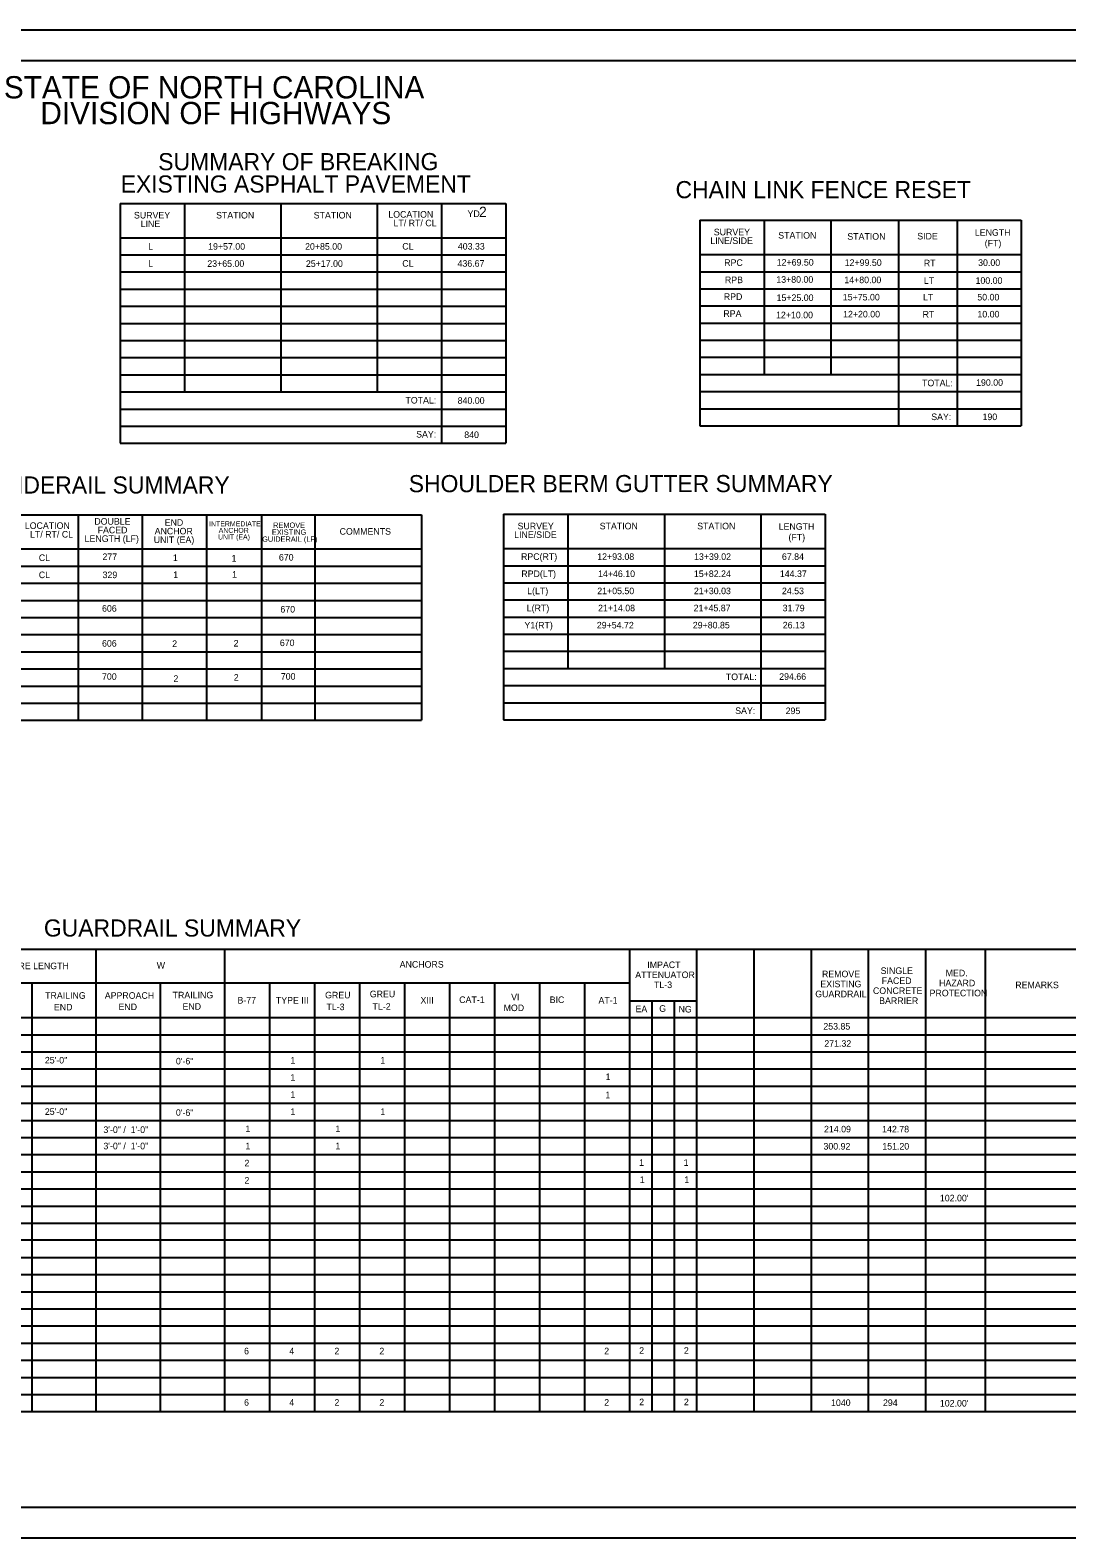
# Model space of a CAD drawing. Extents: x 2820318 to 2824860, y 680532 to 681838.
# Drawn here: x 2823312 to 2824069, y 680532 to 681632 of the extents above; entities that cross this region are included whole.
import ezdxf

# ---------------------------------------------------------------- set-up
doc = ezdxf.new("R2010")
doc.units = 0
for name, color, linetype in [('Default', 7, 'Continuous'), ('Sheet Cutting Line CELL', 7, 'Continuous'), ('Sheet Plot Border Inside CELL', 7, 'Continuous'), ('Sheet Plot Border Outside CELL', 7, 'Continuous'), ('Sheet Summary Combination CELL', 7, 'Continuous'), ('Sheet Summary Combination Grid CELL', 7, 'Continuous')]:
    doc.layers.add(name, color=color, linetype=linetype)

msp = doc.modelspace()

# ---------------------------------------------------------------- linework, layer by layer
at = {"layer": 'Default'}
msp.add_lwpolyline([(2822503.6, 681631.5), (2822503.6, 680531.5), (2824187.6, 680531.5), (2824187.6, 681631.5)], close=True, dxfattribs=at)
msp.add_lwpolyline([(2822503.6, 681631.5), (2822503.6, 680531.5), (2824187.6, 680531.5), (2824187.6, 681631.5)], close=True, dxfattribs=at)
at = {"layer": 'Sheet Cutting Line CELL'}
for p, q in [((2824187.6, 681631.5), (2822503.6, 681631.5)), ((2822503.6, 680531.5), (2824187.6, 680531.5))]:
    msp.add_line(p, q, dxfattribs=at)
at = {"layer": 'Sheet Plot Border Inside CELL'}
msp.add_lwpolyline([(2824183.1, 681609.1), (2822516.6, 681609.1), (2822516.6, 680554), (2824183.1, 680554)], close=True, dxfattribs=at)
at = {"layer": 'Sheet Plot Border Outside CELL'}
msp.add_lwpolyline([(2824187.6, 681631.5), (2822503.6, 681631.5), (2822503.6, 680531.5), (2824187.6, 680531.5)], close=True, dxfattribs=at)
at = {"layer": 'Sheet Summary Combination CELL'}
for p, q in [((2823519.3, 681505.1), (2823519.3, 681505.1)), ((2823534.6, 681505.2), (2823534.6, 681505.2)), ((2823540.2, 681505.1), (2823540.2, 681505.1)), ((2823525.6, 681505), (2823525.6, 681505)), ((2823942.2, 681492.7), (2823942.2, 681492.7)), ((2823948.4, 681492.6), (2823948.4, 681492.6)), ((2823957.5, 681492.8), (2823957.5, 681492.8)), ((2823963.1, 681492.7), (2823963.1, 681492.7)), ((2823799.1, 681278.3), (2823799.1, 681278.3)), ((2823805.3, 681278.2), (2823805.3, 681278.2)), ((2823814.4, 681278.4), (2823814.4, 681278.4)), ((2823820, 681278.3), (2823820, 681278.3))]:
    msp.add_line(p, q, dxfattribs=at)
at = {"layer": 'Sheet Summary Combination Grid CELL'}
for p, q in [((2823378.1, 681505.1), (2823659.4, 681505.1)), ((2823378.1, 681505.1), (2823378.1, 681330.1)), ((2823425, 681505.1), (2823425, 681367.6)), ((2823495.3, 681505.1), (2823495.3, 681367.6)), ((2823565.6, 681505.1), (2823565.6, 681367.6)), ((2823612.5, 681505.1), (2823612.5, 681330.1)), ((2823659.4, 681505.1), (2823659.4, 681330.1)), ((2823800.9, 681492.8), (2824035.4, 681492.8)), ((2823800.9, 681492.8), (2823800.9, 681342.8)), ((2823847.8, 681492.8), (2823847.8, 681380.3)), ((2823896.5, 681492.8), (2823896.5, 681380.3)), ((2823945.7, 681492.8), (2823945.7, 681342.8)), ((2823988.5, 681492.8), (2823988.5, 681342.8)), ((2824035.4, 681492.8), (2824035.4, 681342.8)), ((2823378.1, 681480.1), (2823659.4, 681480.1)), ((2823378.1, 681467.6), (2823659.4, 681467.6)), ((2823800.9, 681467.8), (2824035.4, 681467.8)), ((2823378.1, 681455.1), (2823659.4, 681455.1)), ((2823800.9, 681455.3), (2824035.4, 681455.3)), ((2823378.1, 681442.6), (2823659.4, 681442.6)), ((2823800.9, 681442.8), (2824035.4, 681442.8)), ((2823378.1, 681430.1), (2823659.4, 681430.1)), ((2823800.9, 681430.3), (2824035.4, 681430.3)), ((2823378.1, 681417.6), (2823659.4, 681417.6)), ((2823800.9, 681417.8), (2824035.4, 681417.8)), ((2823378.1, 681405.1), (2823659.4, 681405.1)), ((2823800.9, 681405.3), (2824035.4, 681405.3)), ((2823378.1, 681392.6), (2823659.4, 681392.6)), ((2823800.9, 681392.8), (2824035.4, 681392.8)), ((2823378.1, 681380.1), (2823659.4, 681380.1)), ((2823800.9, 681380.3), (2824035.4, 681380.3)), ((2823378.1, 681367.6), (2823659.4, 681367.6)), ((2823800.9, 681367.8), (2824035.4, 681367.8)), ((2823378.1, 681355.1), (2823659.4, 681355.1)), ((2823800.9, 681355.3), (2824035.4, 681355.3)), ((2823378.1, 681342.6), (2823659.4, 681342.6)), ((2823800.9, 681342.8), (2824035.4, 681342.8)), ((2823378.1, 681330.1), (2823659.4, 681330.1)), ((2823113, 681278), (2823598, 681278)), ((2823347.4, 681278), (2823347.4, 681128)), ((2823394.3, 681278), (2823394.3, 681128)), ((2823441.2, 681278), (2823441.2, 681128)), ((2823481.3, 681278), (2823481.3, 681128)), ((2823520.1, 681278), (2823520.1, 681128)), ((2823598, 681278), (2823598, 681128)), ((2823657.8, 681278.3), (2823892.3, 681278.3)), ((2823657.8, 681278.3), (2823657.8, 681128.3)), ((2823704.7, 681278.3), (2823704.7, 681165.8)), ((2823775.1, 681278.3), (2823775.1, 681165.8)), ((2823845.4, 681278.3), (2823845.4, 681128.3)), ((2823892.3, 681278.3), (2823892.3, 681128.3)), ((2823113, 681253), (2823598, 681253)), ((2823657.8, 681253.3), (2823892.3, 681253.3)), ((2823113, 681240.5), (2823598, 681240.5)), ((2823657.8, 681240.8), (2823892.3, 681240.8)), ((2823113, 681228), (2823551.1, 681228)), ((2823113, 681228), (2823598, 681228)), ((2823657.8, 681228.3), (2823892.3, 681228.3)), ((2823113, 681215.5), (2823598, 681215.5)), ((2823657.8, 681215.8), (2823892.3, 681215.8)), ((2823113, 681203), (2823598, 681203)), ((2823657.8, 681203.3), (2823892.3, 681203.3)), ((2823113, 681190.5), (2823598, 681190.5)), ((2823657.8, 681190.8), (2823892.3, 681190.8)), ((2823113, 681178), (2823598, 681178)), ((2823657.8, 681178.3), (2823892.3, 681178.3)), ((2823113, 681165.5), (2823598, 681165.5)), ((2823657.8, 681165.8), (2823892.3, 681165.8)), ((2823657.8, 681153.3), (2823892.3, 681153.3)), ((2823113, 681153), (2823598, 681153)), ((2823113, 681140.5), (2823551.1, 681140.5)), ((2823113, 681140.5), (2823598, 681140.5)), ((2823657.8, 681140.8), (2823892.3, 681140.8)), ((2823113, 681128), (2823598, 681128)), ((2823657.8, 681128.3), (2823892.3, 681128.3)), ((2822639.6, 680961.1), (2824083.4, 680961.1)), ((2823360.5, 680961.1), (2823360.5, 680711.1)), ((2823454.2, 680961.1), (2823454.2, 680711.1)), ((2823749.5, 680961.1), (2823749.5, 680711.1)), ((2823798.4, 680961.1), (2823798.4, 680711.1)), ((2823840.2, 680961.1), (2823840.2, 680711.1)), ((2823882, 680961.1), (2823882, 680711.1)), ((2823923.8, 680961.1), (2823923.8, 680711.1)), ((2823965.6, 680961.1), (2823965.6, 680623.6)), ((2824009, 680961.1), (2824009, 680623.6)), ((2823749.5, 680936.1), (2823272.4, 680936.1)), ((2823313.6, 680936.1), (2823313.6, 680711.1)), ((2823407.3, 680936.1), (2823407.3, 680711.1)), ((2823487, 680936.1), (2823487, 680711.1)), ((2823519.8, 680936.1), (2823519.8, 680711.1)), ((2823552.7, 680936.1), (2823552.7, 680711.1)), ((2823585.5, 680936.1), (2823585.5, 680711.1)), ((2823618.3, 680936.1), (2823618.3, 680711.1)), ((2823651.1, 680936.1), (2823651.1, 680711.1)), ((2823683.9, 680936.1), (2823683.9, 680711.1)), ((2823716.7, 680936.1), (2823716.7, 680711.1)), ((2823749.5, 680923.4), (2823798.1, 680923.4)), ((2823765.8, 680923.4), (2823765.9, 680711.1)), ((2823782.1, 680923.4), (2823782.2, 680711.1)), ((2822639.6, 680911.1), (2824083.4, 680911.1)), ((2822639.6, 680898.6), (2824083.4, 680898.6)), ((2822639.6, 680886.1), (2824083.4, 680886.1)), ((2822639.6, 680873.6), (2824083.4, 680873.6)), ((2822639.6, 680861.1), (2824083.4, 680861.1)), ((2822639.6, 680848.6), (2824083.4, 680848.6)), ((2822639.6, 680836.1), (2824083.4, 680836.1)), ((2822639.6, 680823.6), (2824083.4, 680823.6)), ((2822639.6, 680811.1), (2824083.4, 680811.1)), ((2822639.6, 680798.6), (2824083.4, 680798.6)), ((2822639.6, 680786.1), (2824083.4, 680786.1)), ((2822639.6, 680773.6), (2824083.4, 680773.6)), ((2822639.6, 680761.1), (2824083.4, 680761.1)), ((2822639.6, 680749), (2824083.4, 680749)), ((2822639.6, 680736.1), (2824083.4, 680736.1)), ((2822639.6, 680723.6), (2824083.4, 680723.6)), ((2822639.6, 680711.1), (2824083.4, 680711.1)), ((2823313.6, 680711.1), (2823313.6, 680623.6)), ((2823360.5, 680711.1), (2823360.5, 680623.6)), ((2823407.3, 680711.1), (2823407.3, 680623.6)), ((2823454.2, 680711.1), (2823454.2, 680623.6)), ((2823487, 680711.1), (2823487, 680623.6)), ((2823519.8, 680711.1), (2823519.8, 680623.6)), ((2823552.7, 680711.1), (2823552.7, 680623.6)), ((2823585.5, 680711.1), (2823585.5, 680623.6)), ((2823618.3, 680711.1), (2823618.3, 680623.6)), ((2823651.1, 680711.1), (2823651.1, 680623.6)), ((2823683.9, 680711.1), (2823683.9, 680623.6)), ((2823716.7, 680711.1), (2823716.7, 680623.6)), ((2823749.5, 680711.1), (2823749.5, 680623.6)), ((2823765.8, 680711.1), (2823765.8, 680623.6)), ((2823782.1, 680711.1), (2823782.2, 680623.6)), ((2823798.4, 680711.1), (2823798.4, 680623.6)), ((2823840.2, 680711.1), (2823840.2, 680623.6)), ((2823882, 680711.1), (2823882, 680623.6)), ((2823923.8, 680711.1), (2823923.8, 680623.6)), ((2822639.6, 680698.6), (2824083.4, 680698.6)), ((2822639.6, 680686.1), (2824083.4, 680686.1)), ((2822639.6, 680673.6), (2824083.4, 680673.6)), ((2822639.6, 680661.1), (2824083.4, 680661.1)), ((2822639.6, 680648.6), (2824083.4, 680648.6)), ((2822639.6, 680636.1), (2824083.4, 680636.1)), ((2822639.6, 680623.6), (2824083.4, 680623.6))]:
    msp.add_line(p, q, dxfattribs=at)

# ---------------------------------------------------------------- texts
at = {"layer": 'Sheet Summary Combination CELL'}
for s, height, p in [('STATE OF NORTH CAROLINA', 16.25, (2823293.3, 681581.7)), ('DIVISION OF HIGHWAYS', 16.25, (2823319.9, 681562.9)), ('SURVEY', 4.8, (2823388.2, 681494.1)), ('STATION', 4.8, (2823448.1, 681494.1)), ('STATION', 4.8, (2823519.3, 681494.1)), ('LOCATION', 4.8, (2823573.7, 681494.7)), ('LINE', 4.8, (2823393.1, 681487.8)), ('LT/ RT/ CL', 4.8, (2823577.5, 681488.4)), ('SURVEY', 4.8, (2823811.1, 681481.8)), ('STATION', 4.8, (2823858.1, 681479.4)), ('STATION', 4.8, (2823908.5, 681478.6)), ('SIDE', 4.8, (2823959.5, 681478.8)), ('LENGTH', 4.8, (2824001.5, 681481.5)), ('L', 4.8, (2823398.6, 681471.4)), ('19+57.00', 4.8, (2823442.3, 681471.3)), ('20+85.00', 4.8, (2823513, 681471.3)), ('CL', 4.8, (2823583.9, 681471.4)), ('403.33', 4.8, (2823624.4, 681471.4)), ('LINE/SIDE', 4.8, (2823808.6, 681475.5)), ('(FT)', 4.8, (2824008.7, 681473.7)), ('L', 4.8, (2823398.6, 681458.9)), ('23+65.00', 4.8, (2823441.7, 681458.8)), ('25+17.00', 4.8, (2823513.6, 681458.8)), ('CL', 4.8, (2823583.9, 681458.9)), ('436.67', 4.8, (2823624.2, 681458.9)), ('RPC', 4.8, (2823818.7, 681459.5)), ('12+69.50', 4.8, (2823857, 681459.7)), ('12+99.50', 4.8, (2823906.6, 681459.5)), ('RT', 4.8, (2823964.3, 681459.2)), ('30.00', 4.8, (2824003.9, 681459.5)), ('RPB', 4.8, (2823819.2, 681446.9)), ('13+80.00', 4.8, (2823856.7, 681447.2)), ('14+80.00', 4.8, (2823906.3, 681446.9)), ('LT', 4.8, (2823964.3, 681446.4)), ('100.00', 4.8, (2824002, 681446.4)), ('RPD', 4.8, (2823818.4, 681434.7)), ('15+75.00', 4.8, (2823905.2, 681434.3)), ('LT', 4.8, (2823963.7, 681434.3)), ('50.00', 4.8, (2824003.3, 681434.3)), ('15+25.00', 4.8, (2823856.9, 681433.9)), ('RPA', 4.8, (2823818.1, 681422.3)), ('12+10.00', 4.8, (2823856.5, 681421.3)), ('12+20.00', 4.8, (2823905.4, 681421.9)), ('RT', 4.8, (2823963.4, 681421.8)), ('10.00', 4.8, (2824003.4, 681421.9)), ('TOTAL:', 4.8, (2823963, 681371.7)), ('190.00', 4.8, (2824002.4, 681372)), ('TOTAL:', 4.8, (2823586.2, 681359.1)), ('840.00', 4.8, (2823624.3, 681358.9)), ('SAY:', 4.8, (2823969.7, 681347)), ('190', 4.8, (2824007.1, 681347)), ('SAY:', 4.8, (2823594, 681334.3)), ('840', 4.8, (2823629.1, 681333.9)), ('DOUBLE', 4.8, (2823359.3, 681270.7)), ('END', 4.8, (2823410.6, 681269.9)), ('LOCATION', 4.8, (2823308.6, 681267.6)), ('LT/ RT/ CL', 4.8, (2823312.4, 681261.3)), ('LENGTH (LF)', 4.8, (2823352.2, 681258.1)), ('FACED', 4.8, (2823361.7, 681264.4)), ('ANCHOR', 4.8, (2823403.3, 681263.6)), ('INTERMEDIATE ', 3.662, (2823443, 681269.5)), ('UNIT (EA)', 3.66, (2823449.5, 681259.9)), ('ANCHOR', 3.66, (2823450, 681264.7)), ('EXISTING', 3.89, (2823488.8, 681263.3)), ('REMOVE', 3.89, (2823489.7, 681268.4)), ('COMMENTS', 4.8, (2823538.2, 681263.4)), ('LINE/SIDE', 4.8, (2823665.5, 681261)), ('SURVEY', 4.8, (2823668, 681267.3)), ('STATION', 4.8, (2823727.9, 681267.3)), ('STATION', 4.8, (2823799, 681267.3)), ('LENGTH', 4.8, (2823858.4, 681267)), ('(FT)', 4.8, (2823865.6, 681259.2)), ('UNIT (EA)', 4.8, (2823402.6, 681257.3)), ('GUIDERAIL (LF)', 3.888, (2823481.7, 681258.2)), ('CL', 4.8, (2823318.8, 681244.2)), ('277', 4.8, (2823365.2, 681244.9)), ('1', 4.8, (2823416.6, 681244.2)), ('1', 4.8, (2823459.4, 681243.8)), ('670', 4.8, (2823493.9, 681244.5)), ('RPC(RT)', 4.8, (2823670.5, 681245)), ('12+93.08', 4.8, (2823726.1, 681245)), ('13+39.02', 4.8, (2823796.7, 681245)), ('67.84', 4.8, (2823860.8, 681245)), ('CL', 4.8, (2823318.8, 681231.7)), ('329', 4.8, (2823365.3, 681231.7)), ('1', 4.8, (2823416.8, 681231.8)), ('1', 4.8, (2823459.8, 681232)), ('RPD(LT)', 4.8, (2823670.7, 681232.5)), ('14+46.10', 4.8, (2823726.7, 681232.5)), ('15+82.24', 4.8, (2823796.6, 681232.5)), ('144.37', 4.8, (2823859.3, 681232.5)), ('L(LT)', 4.8, (2823675, 681220)), ('21+05.50', 4.8, (2823726.1, 681220)), ('21+30.03', 4.8, (2823796.6, 681220)), ('24.53', 4.8, (2823860.8, 681220)), ('606', 4.8, (2823364.9, 681207.2)), ('670', 4.8, (2823495, 681206.6)), ('L(RT)', 4.8, (2823674.7, 681207.5)), ('21+14.08', 4.8, (2823726.7, 681207.5)), ('21+45.87', 4.8, (2823796.4, 681207.5)), ('31.79', 4.8, (2823861.3, 681207.5)), ('Y1(RT)', 4.8, (2823673, 681195)), ('29+54.72', 4.8, (2823725.8, 681195)), ('29+80.85', 4.8, (2823795.8, 681195)), ('26.13', 4.8, (2823861.4, 681195)), ('606', 4.8, (2823364.9, 681181.7)), ('2', 4.8, (2823416.1, 681181.5)), ('2', 4.8, (2823460.9, 681181.8)), ('670', 4.8, (2823494.6, 681182.1)), ('700', 4.8, (2823364.9, 681157.5)), ('2', 4.8, (2823417, 681156)), ('2', 4.8, (2823461, 681156.9)), ('700', 4.8, (2823495.3, 681157.6)), ('TOTAL:', 4.8, (2823819.9, 681157.3)), ('294.66', 4.8, (2823858.8, 681157.5)), ('SAY:', 4.8, (2823826.7, 681132.6)), ('295', 4.8, (2823863.5, 681132.5)), ('GUARDRAIL SUMMARY', 12.5, (2823322.5, 680970.2)), ('FLARE LENGTH', 4.8, (2823292.2, 680946.4)), ('W', 4.8, (2823404.8, 680946.8)), ('ANCHORS', 4.8, (2823582, 680947.5)), ('ATTENUATOR', 4.8, (2823753.8, 680939.9)), ('IMPACT', 4.8, (2823762.6, 680947.2)), ('REMOVE', 4.8, (2823890, 680940.5)), ('SINGLE', 4.8, (2823932.8, 680942.9)), ('MED.', 4.8, (2823980.2, 680941.2)), ('TL-3', 4.8, (2823767.5, 680932.6)), ('EXISTING', 4.8, (2823888.8, 680933.2)), ('CONCRETE', 4.8, (2823927.2, 680928.3)), ('FACED', 4.8, (2823933.6, 680935.6)), ('HAZARD', 4.8, (2823975.4, 680933.9)), ('REMARKS', 4.8, (2824031, 680932.5)), ('TRAILING', 4.8, (2823323.4, 680924.8)), ('APPROACH', 4.8, (2823366.9, 680924.8)), ('TRAILING', 4.8, (2823416.4, 680925.1)), ('B-77', 4.8, (2823463.7, 680921.3)), ('TYPE III', 4.8, (2823491.7, 680921.3)), ('GREU', 4.8, (2823527.6, 680925.1)), ('GREU', 4.8, (2823560.2, 680925.9)), ('XIII', 4.8, (2823597.2, 680921.3)), ('CAT-1', 4.8, (2823625.4, 680921.7)), ('VI', 4.8, (2823663.3, 680923.7)), ('BIC', 4.8, (2823691.4, 680921.7)), ('AT-1', 4.8, (2823727, 680921.3)), ('GUARDRAIL', 4.8, (2823885.1, 680925.9)), ('BARRIER', 4.8, (2823931.7, 680921)), ('PROTECTION', 4.8, (2823968.5, 680926.6)), ('END', 4.8, (2823329.8, 680916.3)), ('END', 4.8, (2823376.9, 680916.5)), ('END', 4.8, (2823423.6, 680916.8)), ('TL-3', 4.8, (2823528.6, 680916.5)), ('TL-2', 4.8, (2823562.2, 680916.8)), ('MOD', 4.8, (2823657.8, 680915.8)), ('EA', 4.8, (2823754, 680915)), ('G', 4.8, (2823771.3, 680915.3)), ('NG', 4.8, (2823785.4, 680914.8)), ('253.85', 4.8, (2823891, 680902.3)), ('271.32', 4.8, (2823891.7, 680889.8)), ('25\'-0"', 4.8, (2823323.2, 680877.6)), ('0\'-6"', 4.8, (2823418.8, 680876.9)), ('1', 4.8, (2823502.3, 680877.5)), ('1', 4.8, (2823567.9, 680877.5)), ('1', 4.8, (2823502.3, 680865)), ('1', 4.8, (2823732.2, 680865.5)), ('1', 4.8, (2823502.3, 680852.5)), ('1', 4.8, (2823732, 680852.2)), ('25\'-0"', 4.8, (2823323.2, 680840.1)), ('0\'-6"', 4.8, (2823418.8, 680839.4)), ('1', 4.8, (2823502.3, 680840)), ('1', 4.8, (2823567.9, 680840)), ('3\'-0" /  1\'-0"', 4.8, (2823365.9, 680826.9)), ('1', 4.8, (2823469.5, 680827.5)), ('1', 4.8, (2823535.1, 680827.5)), ('214.09', 4.8, (2823891.5, 680827.3)), ('142.78', 4.8, (2823933.9, 680827.3)), ('3\'-0" /  1\'-0"', 4.8, (2823365.9, 680815)), ('1', 4.8, (2823469.5, 680815)), ('1', 4.8, (2823535.1, 680815)), ('300.92', 4.8, (2823891.1, 680814.8)), ('151.20', 4.8, (2823934, 680814.8)), ('2', 4.8, (2823468.8, 680802.5)), ('1', 4.8, (2823756.6, 680802.9)), ('1', 4.8, (2823789.1, 680802.9)), ('2', 4.8, (2823468.8, 680790)), ('1', 4.8, (2823757.1, 680790.4)), ('1', 4.8, (2823789.6, 680790.4)), ("102.00'", 4.8, (2823976, 680777)), ('6', 4.8, (2823468.5, 680665.4)), ('4', 4.8, (2823501.5, 680665.4)), ('2', 4.8, (2823534.4, 680665.4)), ('2', 4.8, (2823567.2, 680665.4)), ('2', 4.8, (2823731.2, 680665.4)), ('2', 4.8, (2823756.7, 680665.8)), ('2', 4.8, (2823789.3, 680665.8)), ('6', 4.8, (2823468.5, 680627.9)), ('4', 4.8, (2823501.5, 680627.9)), ('2', 4.8, (2823534.4, 680627.9)), ('2', 4.8, (2823567.2, 680627.9)), ('2', 4.8, (2823731.2, 680627.9)), ('2', 4.8, (2823756.7, 680628.3)), ('2', 4.8, (2823789.3, 680628.3)), ('1040', 4.8, (2823896.6, 680627.7)), ('294', 4.8, (2823934.5, 680627.7)), ("102.00'", 4.8, (2823976, 680627.3))]:
    msp.add_text(s, height=height, dxfattribs=at).set_placement(p)
for s, p in [('SUMMARY OF BREAKING', (2823405.9, 681529.3)), ('EXISTING ASPHALT PAVEMENT', (2823378.5, 681513)), ('CHAIN LINK FENCE RESET', (2823783.2, 681508.9)), ('SHOULDER BERM GUTTER SUMMARY', (2823588.6, 681294.4)), ('CABLE GUIDERAIL SUMMARY', (2823218.4, 681293.4))]:
    msp.add_text(s, height=12.5, rotation=0.0119, dxfattribs=at).set_placement(p)
at = {"layer": 'Sheet Summary Combination Grid CELL'}
for s, height, p in [('YD', 4.8, (2823631.5, 681495.2)), ('2', 7.5, (2823639.9, 681495.2))]:
    msp.add_text(s, height=height, dxfattribs=at).set_placement(p)

doc.saveas('drawing.dxf')
